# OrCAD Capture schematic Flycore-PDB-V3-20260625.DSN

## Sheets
1 PAGE03_DCDC: size C; title: 分电板; rev: <1>; note: PAGE03_DCDC
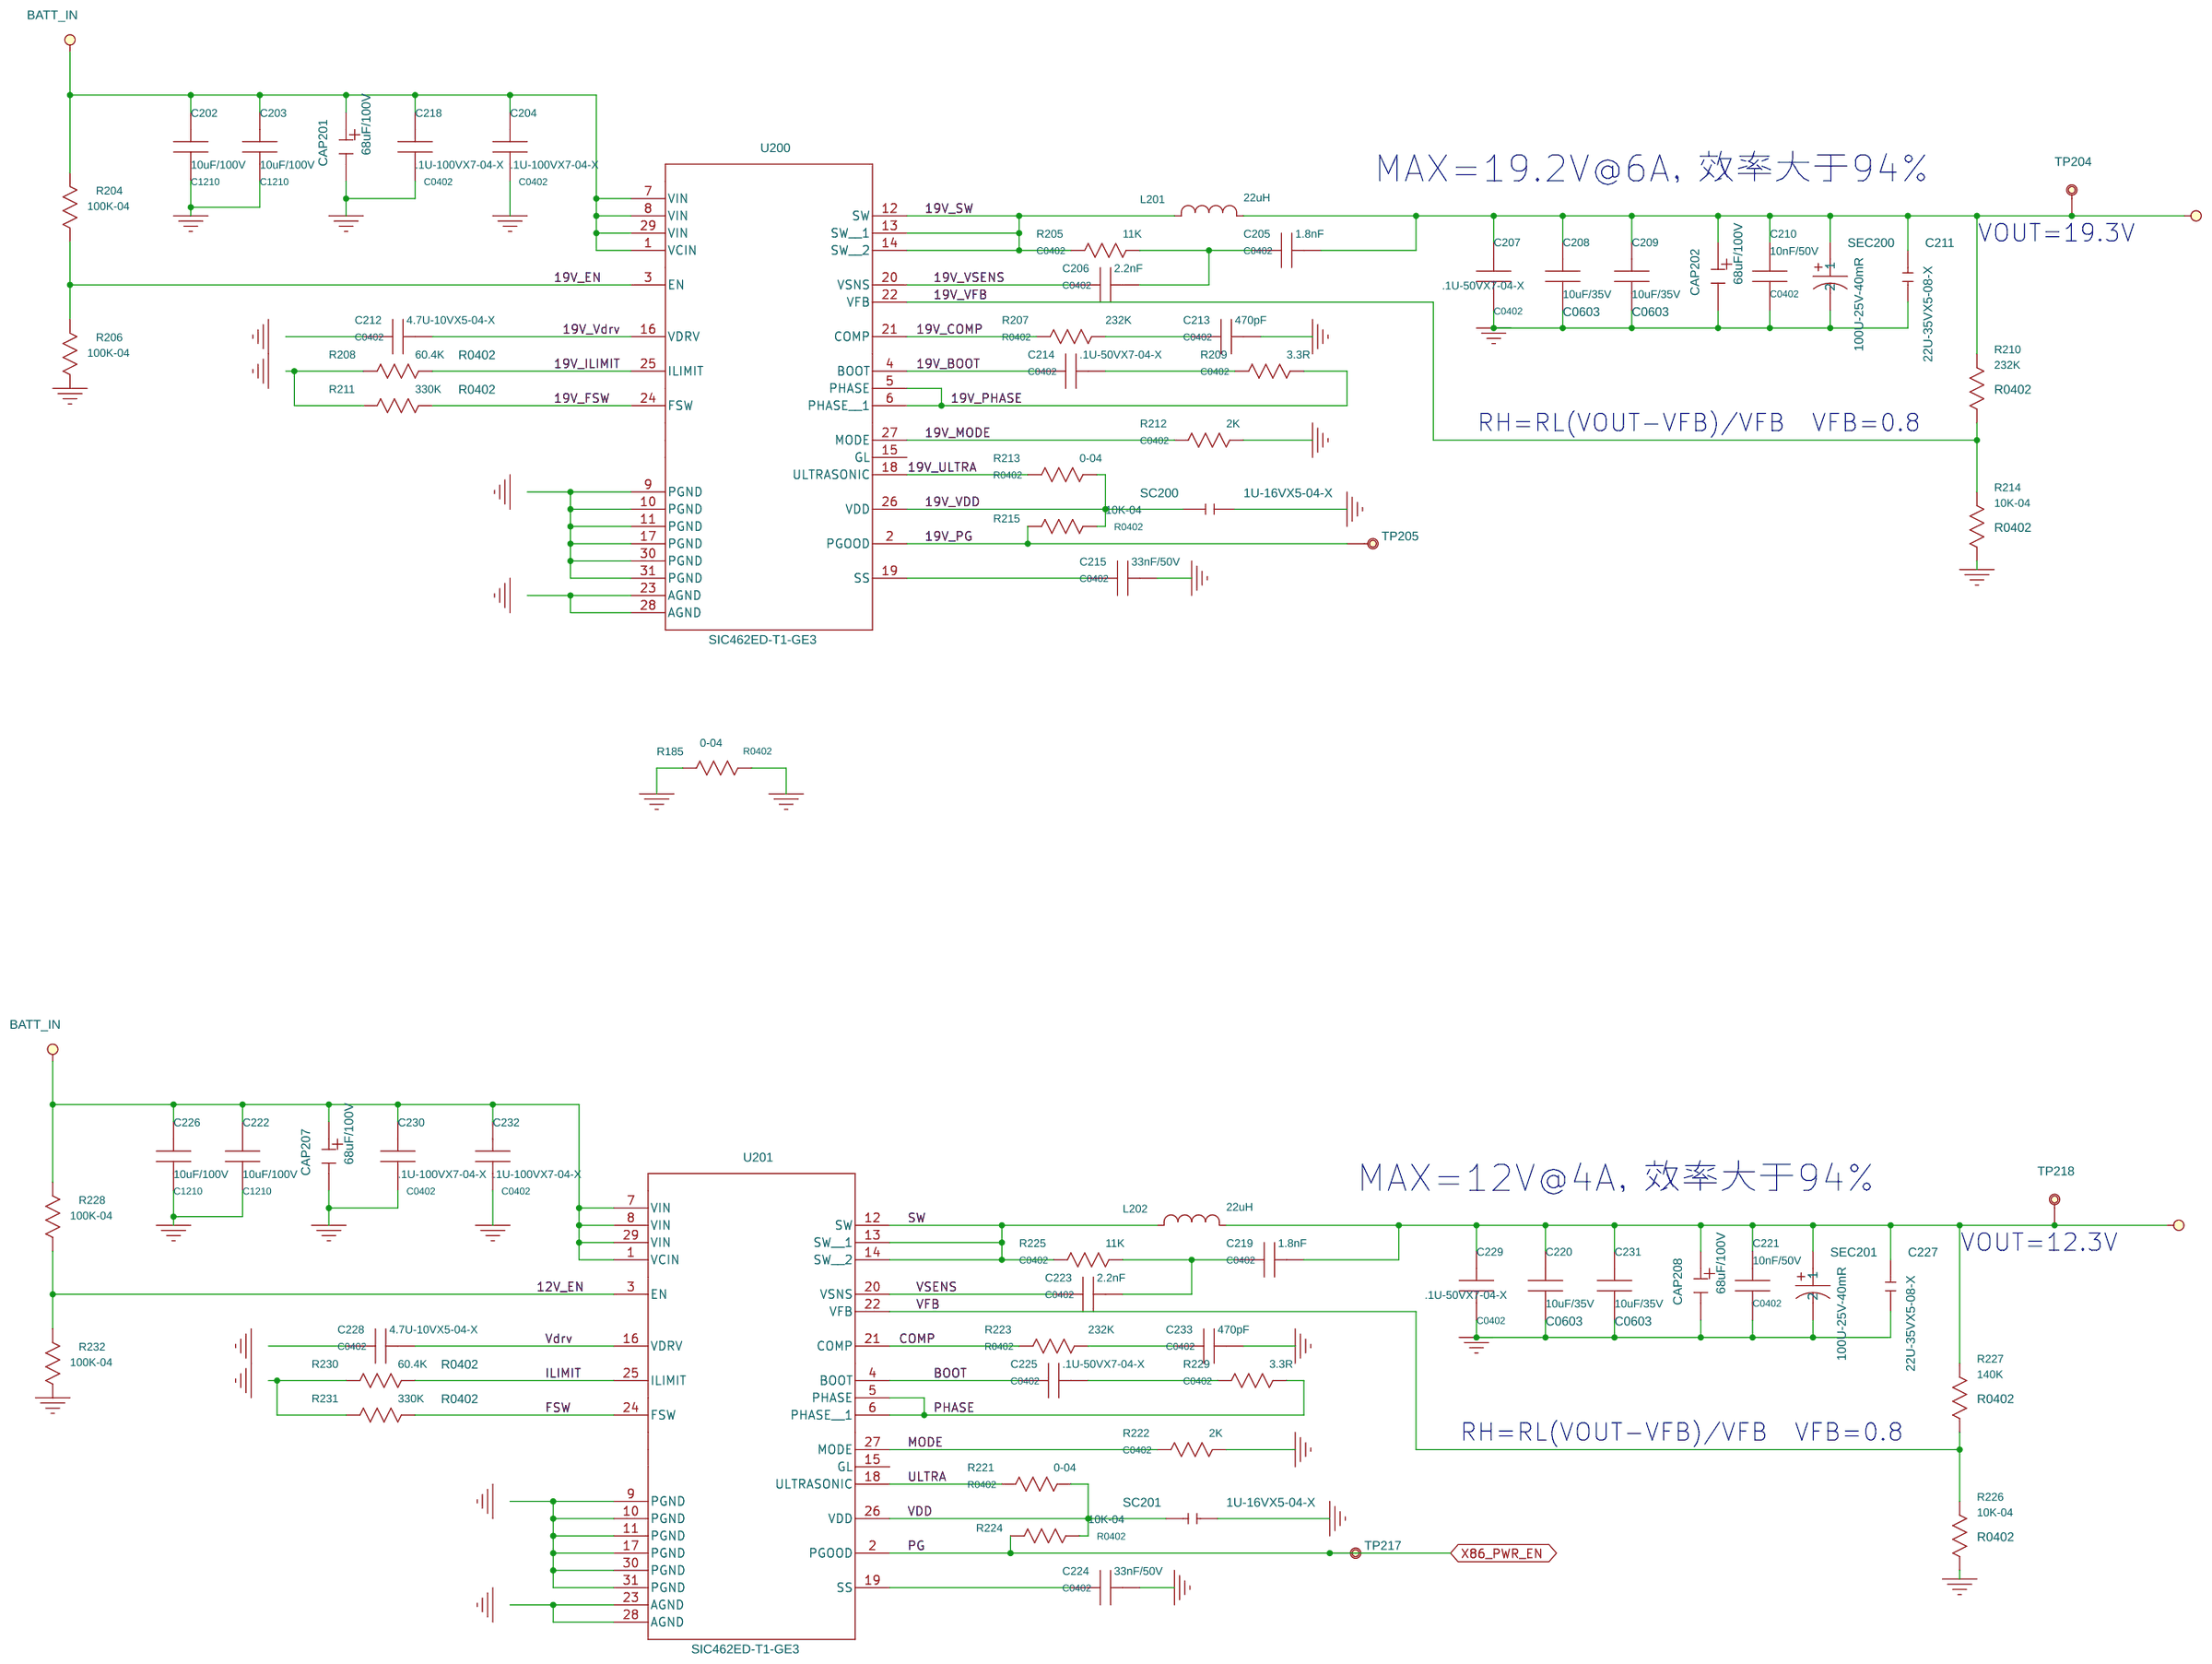
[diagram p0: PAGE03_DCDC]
2 PAGE01_Block Diagram: note: BLOCK DIAGRAM
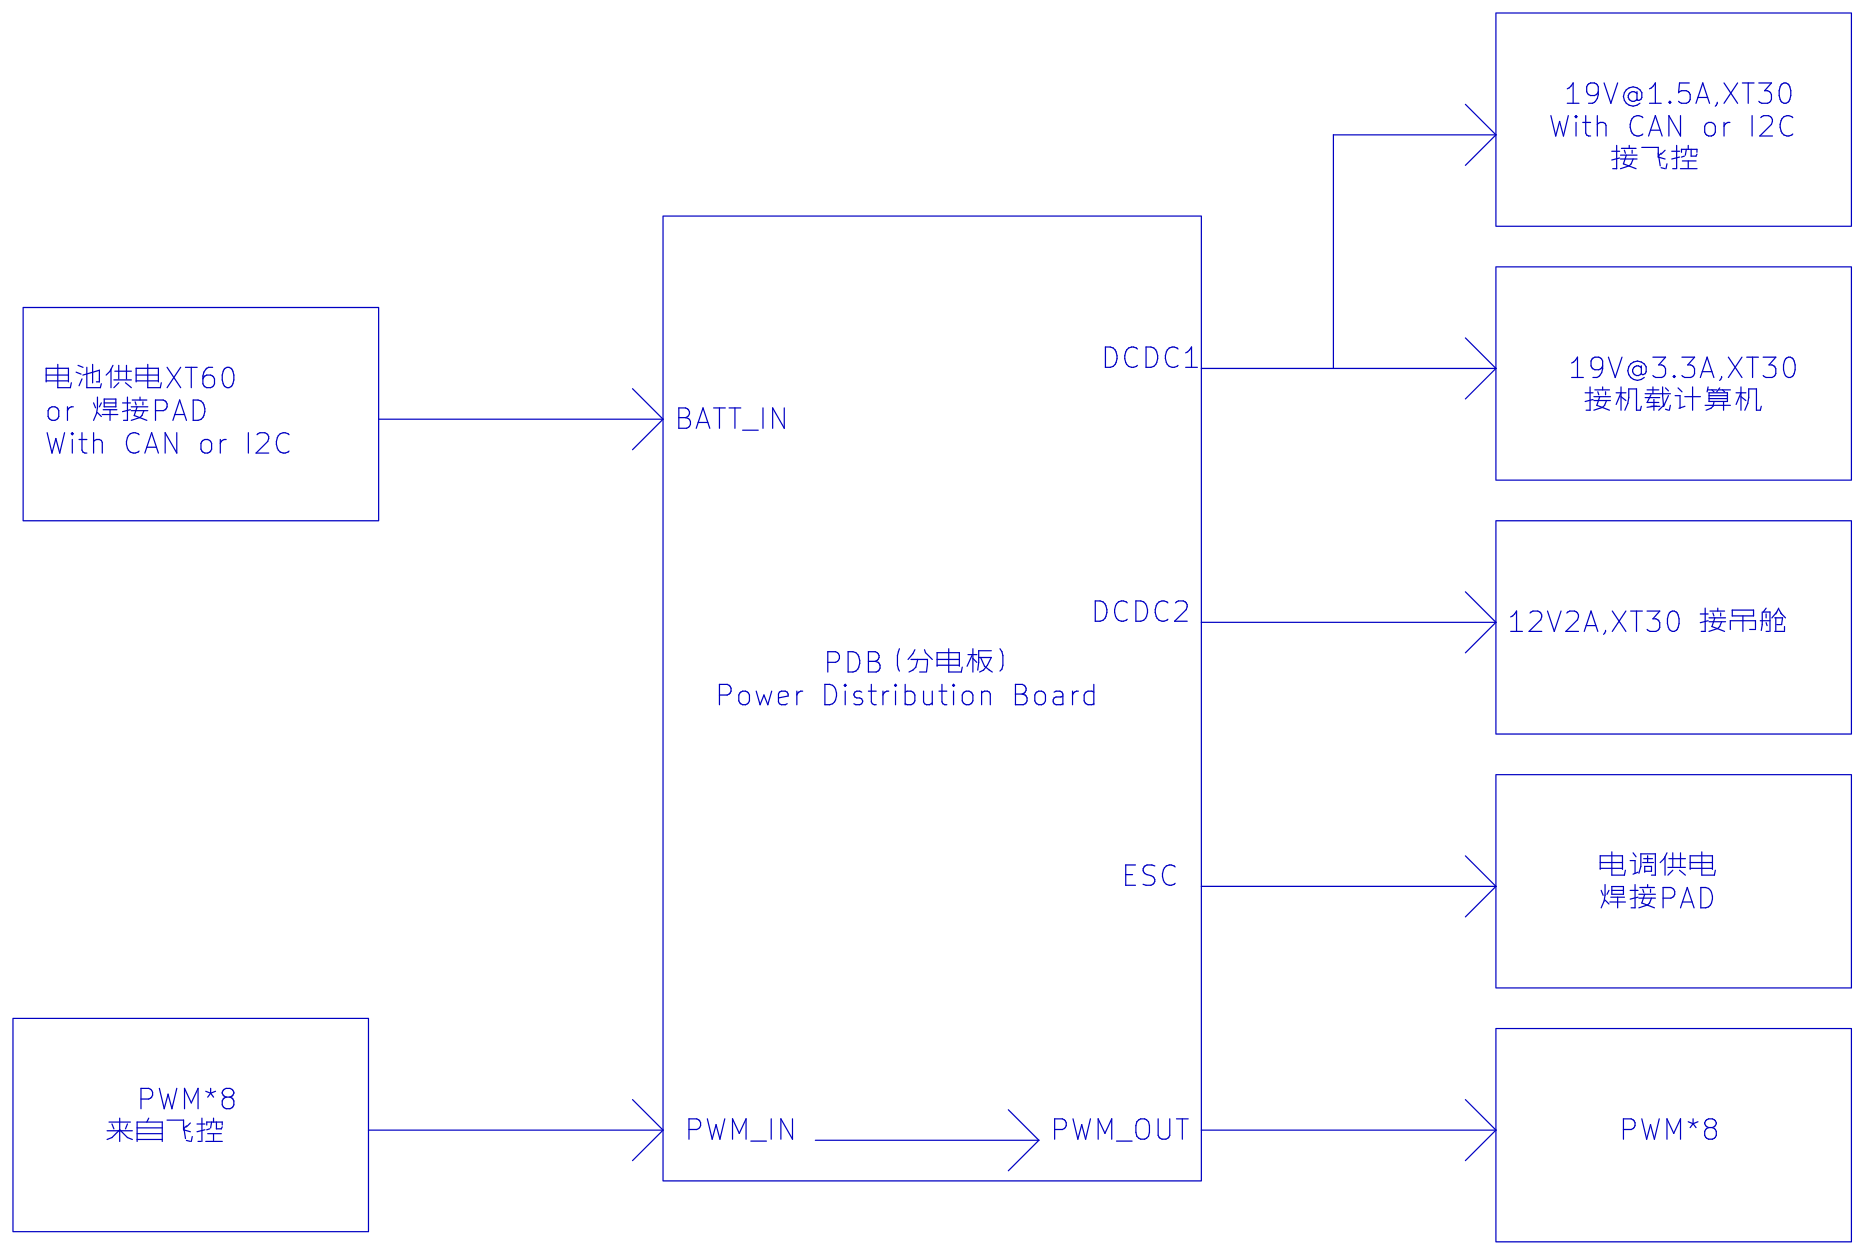
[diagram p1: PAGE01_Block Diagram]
3 PAGE02_Power_Switch: size C; note: PAGE02_Power_Switch
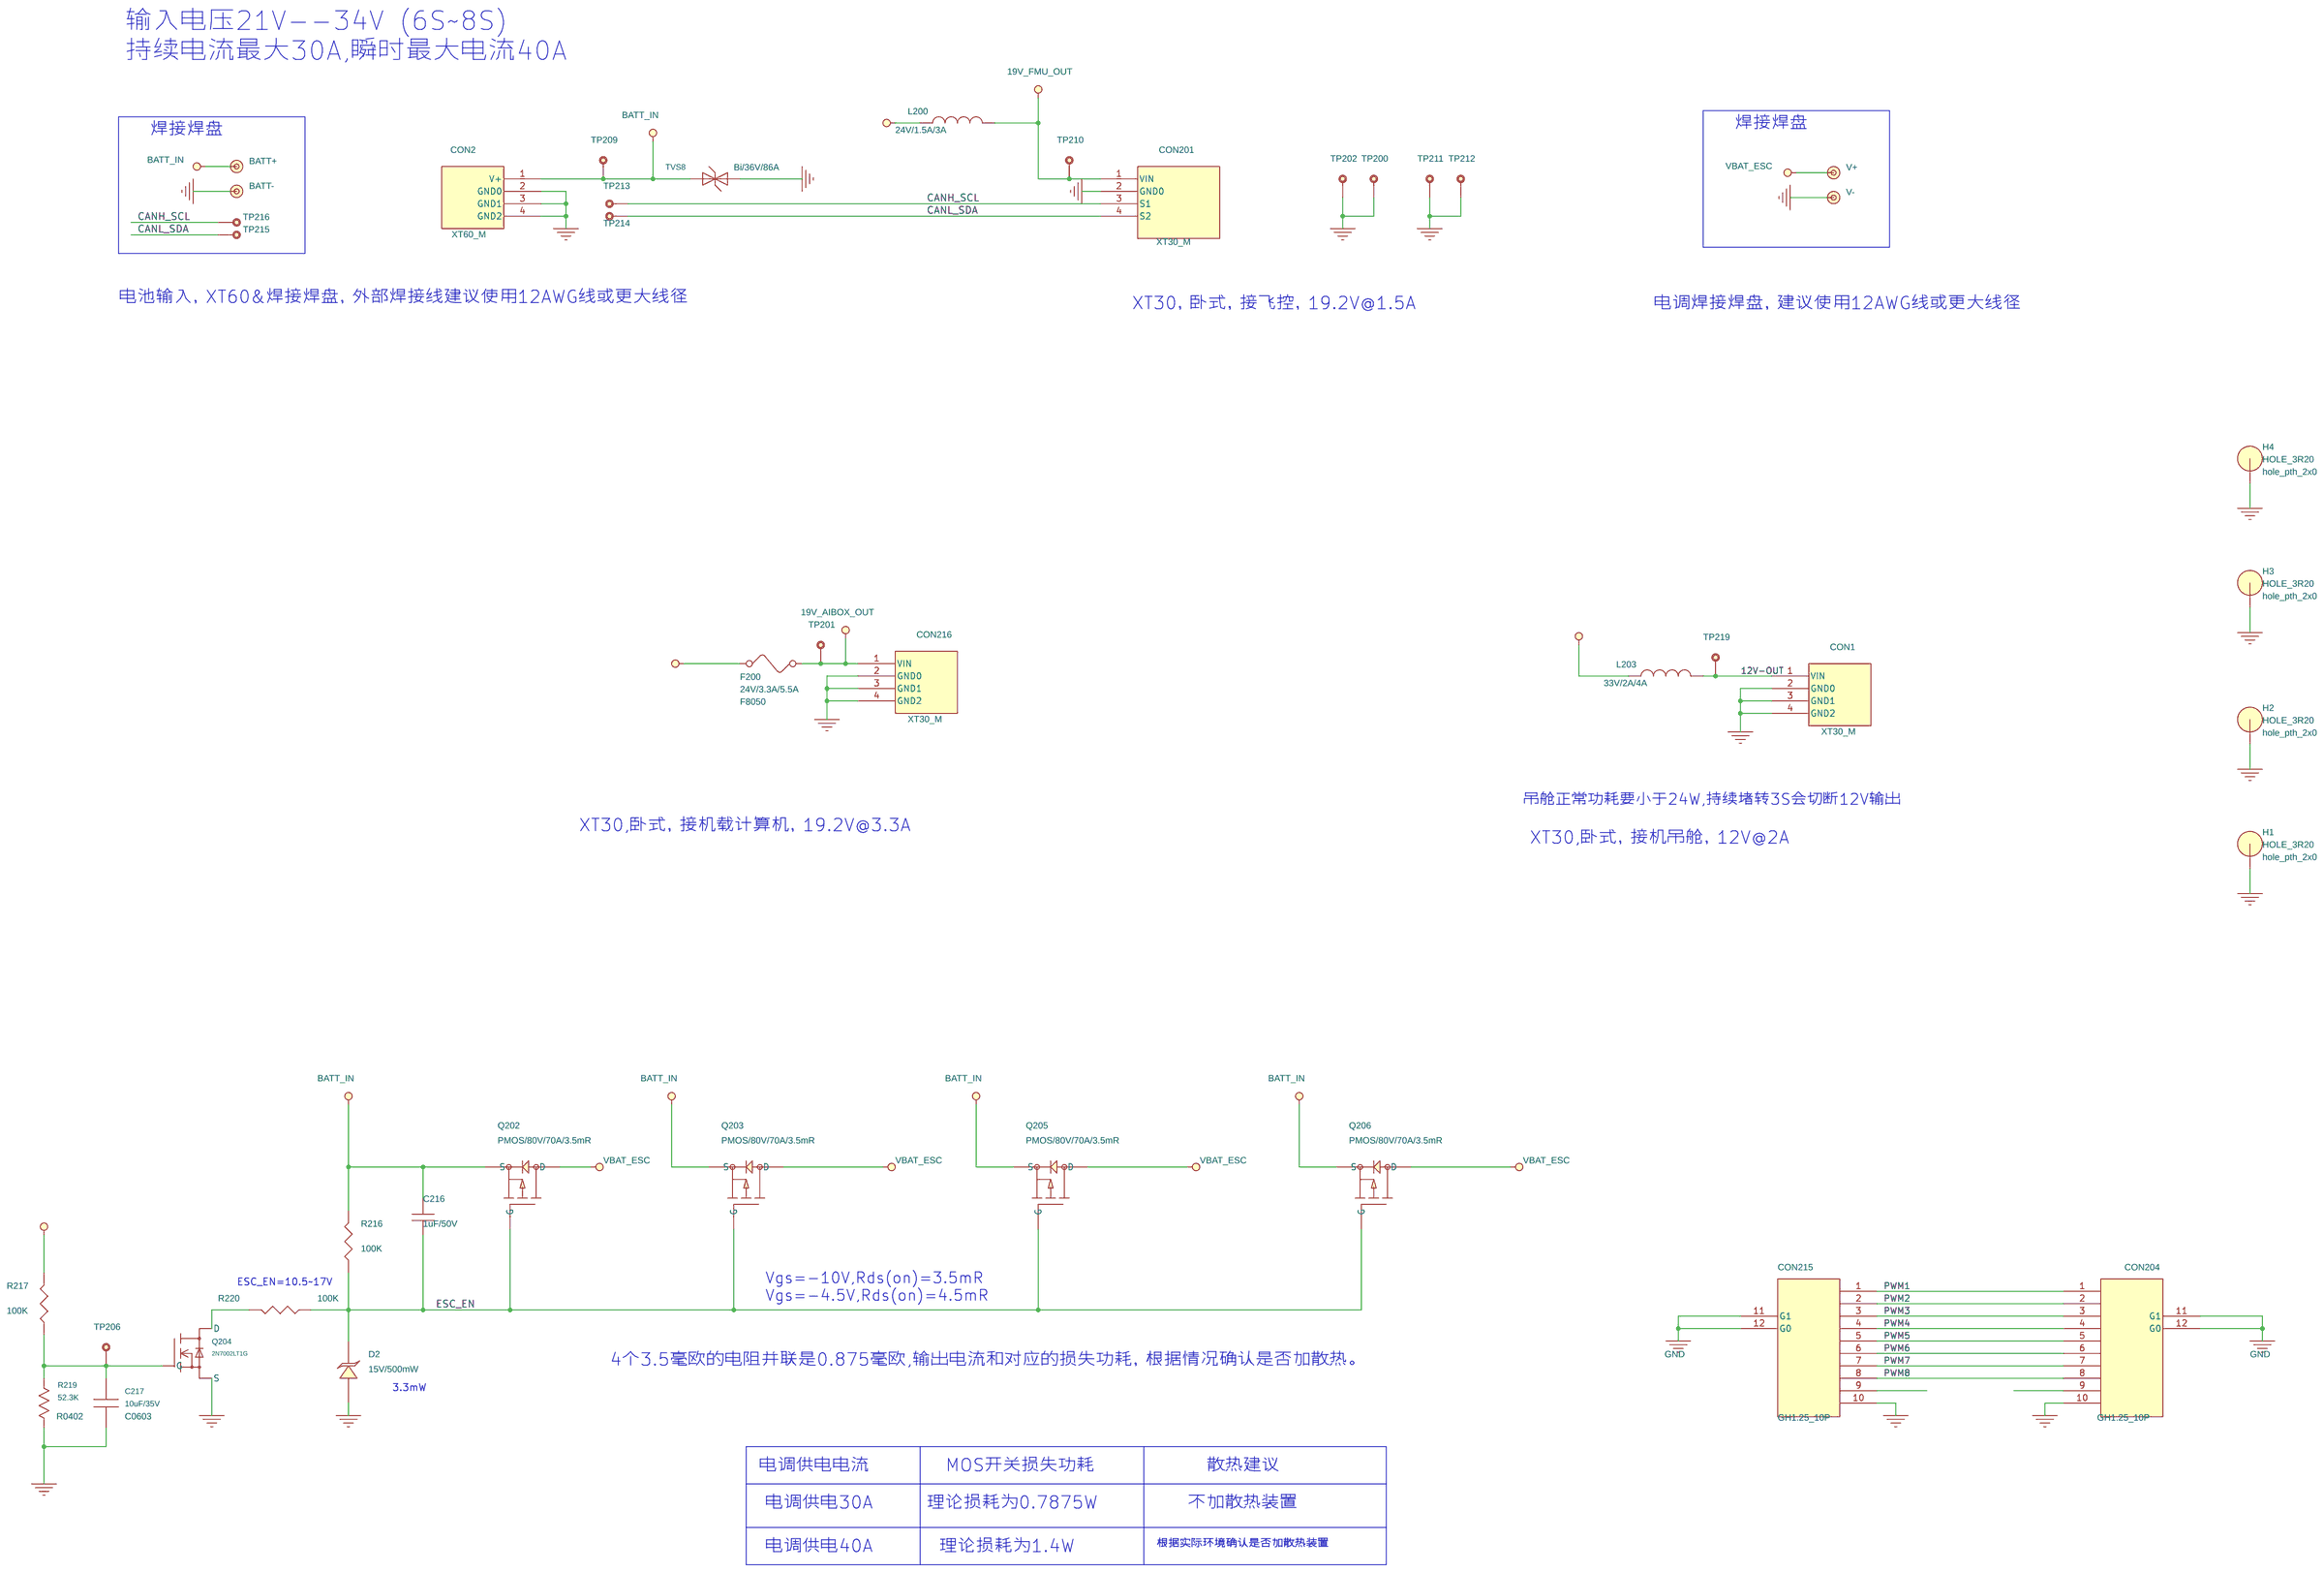
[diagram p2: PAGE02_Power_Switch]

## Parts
sheet PAGE02_Power_Switch
BATT+  TP-SMD  [tp_smd_rect_3r0x4r0]
BATT-  TP-SMD  [tp_smd_rect_3r0x4r0]
C216  1uF/50V  [C0402]
C217  10uF/35V  [C0603]
CON1  XT30_M  [XT30_M]
CON2  XT60_M  [AMASS_XT60PW-M]
CON201  XT30_M  [AMASS_XT30PW2]
CON204  GH1.25_10P  [gh1x25_10_li]
CON215  GH1.25_10P  [gh1x25_10_li]
CON216  XT30_M  [XT30_M]
D2  15V/500mW  [SOD-123]
F200  24V/3.3A/5.5A  [F8050]
H1  HOLE_3R20  [hole_pth_2x0]
H2  HOLE_3R20  [hole_pth_2x0]
H3  HOLE_3R20  [hole_pth_2x0]
H4  HOLE_3R20  [hole_pth_2x0]
L200  24V/1.5A/3A  [C1206]
L203  33V/2A/4A  [r2512]
Q202  PMOS/80V/70A/3.5mR  [to252-3_4r56]
Q203  PMOS/80V/70A/3.5mR  [to252-3_4r56]
Q204  Q_FET_N_ENH  [sot23d132_1_2]
Q205  PMOS/80V/70A/3.5mR  [to252-3_4r56]
Q206  PMOS/80V/70A/3.5mR  [to252-3_4r56]
R216  100K  [R0402]
R217  100K  [R0402]
R219  52.3K  [R0402]
R220  100K  [R0402]
TP200  TP  [testpoint_59mil]
TP201  TP  [testpoint_59mil]
TP202  TP  [testpoint_59mil]
TP206  TP  [testpoint_59mil]
TP209  TP  [testpoint_59mil]
TP210  TP  [testpoint_59mil]
TP211  TP  [testpoint_59mil]
TP212  TP  [testpoint_59mil]
TP213  TP  [testpoint_59mil]
TP214  TP  [testpoint_59mil]
TP215  TP  [testpoint_59mil]
TP216  TP  [testpoint_59mil]
TP219  TP  [testpoint_59mil]
TVS8  Bi/36V/86A  [smc_do-214ab]
V+  TP-SMD  [tp_smd_rect_3r0x4r0]
V-  TP-SMD  [tp_smd_rect_3r0x4r0]
sheet PAGE03_DCDC
C202  10uF/100V  [C1210]
C203  10uF/100V  [C1210]
C204  .1U-100VX7-04-X  [C0402]
C205  1.8nF  [C0402]
C206  2.2nF  [C0402]
C207  .1U-50VX7-04-X  [C0402]
C208  10uF/35V  [C0603]
C209  10uF/35V  [C0603]
C210  10nF/50V  [C0402]
C211  22U-35VX5-08-X  [C0805]
C212  4.7U-10VX5-04-X  [C0402]
C213  470pF  [C0402]
C214  .1U-50VX7-04-X  [C0402]
C215  33nF/50V  [C0402]
C218  .1U-100VX7-04-X  [C0402]
C219  1.8nF  [C0402]
C220  10uF/35V  [C0603]
C221  10nF/50V  [C0402]
C222  10uF/100V  [C1210]
C223  2.2nF  [C0402]
C224  33nF/50V  [C0402]
C225  .1U-50VX7-04-X  [C0402]
C226  10uF/100V  [C1210]
C227  22U-35VX5-08-X  [C0805]
C228  4.7U-10VX5-04-X  [C0402]
C229  .1U-50VX7-04-X  [C0402]
C230  .1U-100VX7-04-X  [C0402]
C231  10uF/35V  [C0603]
C232  .1U-100VX7-04-X  [C0402]
C233  470pF  [C0402]
CAP201  68uF/100V  [cap_smd_330_D10]
CAP202  68uF/100V  [cap_smd_330_D10]
CAP207  68uF/100V  [cap_smd_330_D10]
CAP208  68uF/100V  [cap_smd_330_D10]
L201  22uH  [L_11X15_10X85]
L202  22uH  [L_11X15_10X85]
R185  0-04  [R0402]
R204  100K-04  [C0402]
R205  11K  [C0402]
R206  100K-04  [C0402]
R207  232K  [R0402]
R208  60.4K  [R0402]
R209  3.3R  [C0402]
R210  232K  [R0402]
R211  330K  [R0402]
R212  2K  [C0402]
R213  0-04  [R0402]
R214  10K-04  [R0402]
R215  10K-04  [R0402]
R221  0-04  [R0402]
R222  2K  [C0402]
R223  232K  [R0402]
R224  10K-04  [R0402]
R225  11K  [C0402]
R226  10K-04  [R0402]
R227  140K  [R0402]
R228  100K-04  [C0402]
R229  3.3R  [C0402]
R230  60.4K  [R0402]
R231  330K  [R0402]
R232  100K-04  [C0402]
SC200  1U-16VX5-04-X  [C0402]
SC201  1U-16VX5-04-X  [C0402]
SEC200  100U-25V-40mR  [C7343]
SEC201  100U-25V-40mR  [C7343]
TP204  TP  [testpoint_59mil]
TP205  TP  [testpoint_59mil]
TP217  TP  [testpoint_59mil]
TP218  TP  [testpoint_59mil]
U200  SIC462ED-T1-GE3  [VREG_SIC462ED-T1-GE3]
U201  SIC462ED-T1-GE3  [VREG_SIC462ED-T1-GE3]

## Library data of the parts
BATT+ BATT- V+ V- = TP: 测试点; BOM_Manufacturer_Part: PART_NUM; OPTION: 不焊接; PRICE: 0; SMTProperty: 不焊接
C216 = CAP_0: MANUFACTURER: YAGEO; MPN: CC0402KRX5R8BB104; Manufacture: HRE; part number: CGA0402X5R105K500GT
C208 C209 C217 C220 C231 = C#1: MANUFACTURER: muRata; Manufacture: muRata; part number: GRM188R6YA106MA73D
CON1 CON216 = XT30_M: Manufacture: AMASS; part number: XT30PW-M
CON2 = XT30_M_51: Manufacture: AMASS; part number: XT60PW_M
CON201 = XT30_M_46: Manufacture: AMASS; part number: XT30PW(2+2)-M.G.B
CON204 CON215 = XT30_M_5: MANUFACTURER: JST; Manufacture: JST; part number: GH125-S10CCA-00
D2 = TVS_0: ERP类型: TVS; Manufacture: MDD(辰达半导体); part number: BZT52C15
F200 = FUSE: 保险丝，Vmax=16V,Imax=100A，Icurrent=8A,Ri=0.028ohm; Created by: JJJ; Manufacture: Littelfuse; Manufacturer: 金瑞电子; Manufacturer Part Number: Q/JKTD-16-200; Priority: A; RK PN: Q/JKTD-16-200; part number: 2920L330/24MR
H1-H4 = Hole: 直径3.2mm螺丝孔,无铜柱; Created by: YWQ; Part Type: HOLE; Priority: A
L200 = INDUCTOR: 抗30±10Ω,最大直流电阻（DCR）0.01Ω，最大电流6A; Manufactory Footprint: L0805; Manufactory Name: TDK; Manufacture: LUTE; Material Code: 503040004; Optimum Level: D; Ordering Information: MPZ2012S300A; Part Type: Bead; Quality Level: I; part number: 1206L150/24NR
L203 = INDUCTOR: 抗30±10Ω,最大直流电阻（DCR）0.01Ω，最大电流6A; Manufactory Footprint: L0805; Manufactory Name: TDK; Manufacture: LUTE; Material Code: 503040004; Optimum Level: D; Ordering Information: MPZ2012S300A; Part Type: Bead; Quality Level: I; part number: 2512L200/33GR
Q202 Q203 Q205 Q206 = PMOS-1: P-Mos,SOT-23,CJ2303,30V,330mΩ@4.5V,JCET,CJ2303,3*2.55*1.15; MF_PARTNUMBER: CJ2303; Manufacture: HUASHUO; PART_TYPE: P-Mos; part number: HSU4119; Datasheet: L:\Skysofy-SPEC\Mos&Tri&Dio_ITEMS\222-0003-001.pdf
Q204 = Q_FET_N_ENH#1: ASSEMBLY: M2_WIFIBT; CDS_LIB: discrete; CDS_LOCATION: Q17; CDS_PART_NAME: Q_FET_N_ENH_DFN1006-DMN26D0UFB4,20V,999MOHM@10V / 3000MOHM@4.5V / 4000MOHM@2.5V,0.14A,0.805A,10V,0.35W,999NC@10V / 0NC@4.5V / A; CDS_PHYS_PART_NAME: Q_FET_N_ENH_DFN1006-DMN26D0UFB4,20V,999MOHM@10V / 3000MOHM@4.5V / 4000MOHM@2.5V,0.14A,0.805A,10V,0.35W,999NC@10V / 0NC@4.5V / B; CDS_SEC: 1; CONTINUOUS_CURRENT: 0.14A; CaptureCellPackProp: Q_FET_N_ENH##1; DEVICE_TYPENAME: Q_FET_N_ENH_DFN1006-DMN26D0UFB420V999MOHM10V3000MOHM45V4000MOHM25V014A0805A10V035W999NC10V0NC45VB; DRAWING: #NAME?; LOCATION: Q17; MAX_CURRENT: 0.805A; MAX_VOLTAGE: 20V; MAX_WATTAGE: 0.35W; Manufacture: onsemi; NV_NAME: 2N7002LT1G; NV_PN: 300-0868-000; PACK_TYPE: DFN1006; PATH: I73; part number: 2N7002LT1G
R216 R220 = R_v3: RES,0402,100K,1/16W,5%,RALEC旺诠,RTT02104JTH,1.0*0.5*0.35; MF_PARTNUMBER: RTT02104JTH; Manufacture: YAGEO; PART_TYPE: RES; part number: RC0402FR-07100KL; Datasheet: L:\Skysofy-SPEC\RLC_ITEMS\100-0024-002.pdf
R217 = R_v3: RES,0402,10K,1/16W,5%,RALEC旺诠,RTT02103JTH,1.0*0.5*0.35; MF_PARTNUMBER: RTT02103JTH; Manufacture: YAGEO; PART_TYPE: RES; part number: RC0402FR-07100KL; Datasheet: L:\Skysofy-SPEC\RLC_ITEMS\100-0026-002.pdf
R219 = R: Manufacture: FOJAN; part number: FRC0402F5232TS
TP200-TP202 TP204-TP206 TP209-TP219 = TP_v2: I16774898: I16774971
TVS8 = D_ESD: Manufacture: DOWO; part number: 5.0SMDJ36CA
C202 C203 C222 C226 = C#1: MANUFACTURER: muRata; Manufacture: PSA; part number: FS32X106K101EGG
C204 C218 C230 C232 = C#1: MANUFACTURER: muRata; Manufacture: muRata; part number: GRM155R62A104KE14D
C205 C219 = C#1: MANUFACTURER: muRata; Manufacture: YAGEO; part number: CC0402KRX7R9BB182
C206 C223 = C#1: MANUFACTURER: muRata; Manufacture: muRata; part number: GRM1555C1H222GA01D
C207 C214 C225 C229 = C#1: MANUFACTURER: muRata; Manufacture: YAGEO; part number: CC0402KRX7R9BB104
C210 C221 = C#1: MANUFACTURER: muRata; Manufacture: YAGEO; part number: CC0402KRX7R9BB103
C211 C227 = C0805: C/C.10uF.25V.10%..X5R..T=1.25mm..SMD 0805....LEAD-FREE(RoHS/HF)..; INVENTORY_ON_HAND: 1,743,250; Item_Status: Active; Manufacture: TDK; Part Number: C2012X5R1V226MT000E; Part Type: SMT; VMI_HUB_ON_HAND: 586,000
C212 C228 = C#1: MANUFACTURER: muRata; Manufacture: SAMSUNG; part number: CL05A475KP5NRNC
C213 C233 = C#1: MANUFACTURER: muRata; Manufacture: muRata; part number: GRM1555C1H471JA01D
C215 C224 = C#1: MANUFACTURER: muRata; Manufacture: FOJAN; part number: FCC0402B333K500AT
CAP201 CAP202 CAP207 CAP208 = ECP_0: 贴片电解电容; HelpURL: https://item.szlcsc.com/345306.html; Manufacture: HONOR(荣誉); PRICE: 0.6241; T_TEMPERATURE: -55℃~+155℃; Tolerance: 20%; Vendor: CX(承兴); Vendor P/N: 250AVHA470M0606; part number: HV2A686M1010PZ; 耐压: 25V
L201 L202 = L: Manufacture: PROD; part number: PSPMAA1082T-220M-CGP
R185 R213 R221 = R: Manufacture: UNI-ROYAL; part number: 0402WGF0000TCE
R204 R206 R228 R232 = R: Manufacture: UNI-ROYAL; part number: 0402WGF1003TCE
R205 R225 = R: Manufacture: FOJAN; part number: FRC0402J113 TS
R207 R210 R223 = R: Manufacture: FOJAN; part number: FRC0402F2323TS
R208 R230 = R: Manufacture: FOJAN; part number: FRC0402F6042TS
R209 R229 = R: Manufacture: FOJAN; part number: FRC0402F3R30TS
R211 R231 = R: Manufacture: FOJAN; part number: FRC0402F3303TS
R212 R222 = R: Manufacture: FOJAN; part number: FRC0402F2001TS
R214 R215 R224 R226 = R: Manufacture: UNI-ROYAL; part number: 0402WGF1002TCE
R227 = R: Manufacture: FOJAN; part number: FRC0402F1433TS
SC200 SC201 = C0402: C/C.1uF.6.3V.10%..X5R....SMD 0402....LEAD-FREE(RoHS/HF).; INVENTORY_ON_HAND: 3,432,041; Item_Status: Active; Manufacture: SAMSUNG; Part Number: CL05A105KO5NNNC; Part Type: SMT; VMI_HUB_ON_HAND: 8,620,000
SEC200 SEC201 = CAPACITOR_POL_0: T/C POLYMER.33uF.16V.20%.90m OHM...105C..16TQC33MYFB.SMD B2....LEAD-FREE(RoHS/HF).PANASONIC; Manufacture: KEMET; Part Number: T521D107M025ATE040
U200 U201 = SIC462ED-T1-GE3_7: Manufacture: VISHAY

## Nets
12V-OUT: CON1.1(VIN) L203.2 TP219.1
12V_EN: R228.2 R232.1 U201.3(EN)
19V_AIBOX_OUT: CON216.1(VIN) F200.2 TP201.1
19V_BOOT: C214.1 U200.4(BOOT)
19V_COMP: R207.1 U200.21(COMP)
19V_EN: R204.2 R206.1 U200.3(EN)
19V_FMU_OUT: CON201.1(VIN) L200.2 TP210.1
19V_FSW: R211.2 U200.24(FSW)
19V_ILIMIT: R208.2 U200.25(ILIMIT)
19V_MODE: R212.1 U200.27(MODE)
19V_PG: R215.1 TP205.1 U200.2(PGOOD)
19V_PHASE: R209.2 U200.5(PHASE) U200.6(PHASE__1)
19V_SW: L201.1 R205.1 U200.12(SW) U200.13(SW__1) U200.14(SW__2)
19V_ULTRA: R213.1 U200.18(ULTRASONIC)
19V_VDD: R213.2 R215.2 SC200.1 U200.26(VDD)
19V_Vdrv: C212.1 U200.16(VDRV)
19V_VFB: R210.2 R214.1 U200.22(VFB)
19V_VSENS: C206.2 U200.20(VSNS)
AGND: C204.2 C213.1 C215.2 C224.2 C232.2 C233.1 R185.1 R208.1 R211.1 R212.2 R214.2 R222.2 R226.2 R230.1 R231.1 SC200.2 SC201.2 U200.23(AGND) U200.28(AGND) U201.23(AGND) U201.28(AGND)
GND: BATT-.1 C202.2 C203.2 C207.2 C208.2 C209.2 C210.2 C211.2 C212.2 C217.2 C218.2 C220.2 C221.2 C222.2 C226.2 C227.2 C228.2 C229.2 C230.2 C231.2 CAP201.2 CAP202.2 CAP207.2 CAP208.2 CON1.2(GND0) CON1.3(GND1) CON1.4(GND2) CON2.2(GND0) CON2.3(GND1) CON2.4(GND2) CON201.2(GND0) CON204.10 CON204.11(G1) CON204.12(G0) CON215.10 CON215.11(G1) CON215.12(G0) CON216.2(GND0) CON216.3(GND1) CON216.4(GND2) D2.2(ANODE) H1.1 H2.1 H3.1 H4.1 Q204.2(S) R185.2 R206.2 R219.1 R232.2 SEC200.2 SEC201.2 TP200.1 TP202.1 TP211.1 TP212.1 TVS8.2 U200.9(PGND) U200.10(PGND) U200.11(PGND) U200.17(PGND) U200.30(PGND) U200.31(PGND) U201.9(PGND) U201.10(PGND) U201.11(PGND) U201.17(PGND) U201.30(PGND) U201.31(PGND) V-.1
VBAT_ESC: Q202.3(D) Q203.3(D) Q205.3(D) Q206.3(D) V+.1
VDD: R221.2 R224.2 SC201.1 U201.26(VDD)
VDD_12V_SYS: C219.1 C220.1 C221.1 C227.1 C229.1 C231.1 CAP208.1 L202.2 L203.1 R227.1 SEC201.1 TP218.1
VDD_19V_SYS: C205.1 C207.1 C208.1 C209.1 C210.1 C211.1 CAP202.1 F200.1 L200.1 L201.2 R210.1 R217.2 SEC200.1 TP204.1
BATT_IN: BATT+.1 C202.1 C203.1 C204.1 C216.2 C218.1 C222.1 C226.1 C230.1 C232.1 CAP201.1 CAP207.1 CON2.1(V+) Q202.2(S) Q203.2(S) Q205.2(S) Q206.2(S) R204.1 R216.2 R228.1 TP209.1 TVS8.1 U200.1(VCIN) U200.7(VIN) U200.8(VIN) U200.29(VIN) U201.1(VCIN) U201.7(VIN) U201.8(VIN) U201.29(VIN)
BOOT: C225.1 U201.4(BOOT)
CANH_SCL: CON201.3(S1) TP213.1 TP216.1
CANL_SDA: CON201.4(S2) TP214.1 TP215.1
COMP: R223.1 U201.21(COMP)
ESC_EN: C216.1 D2.1(CATHODE) Q202.1(G) Q203.1(G) Q205.1(G) Q206.1(G) R216.1 R220.1
FSW: R231.2 U201.24(FSW)
ILIMIT: R230.2 U201.25(ILIMIT)
MODE: R222.1 U201.27(MODE)
PHASE: R229.2 U201.5(PHASE) U201.6(PHASE__1)
PWM1: CON204.1 CON215.1
PWM2: CON204.2 CON215.2
PWM3: CON204.3 CON215.3
PWM4: CON204.4 CON215.4
PWM5: CON204.5 CON215.5
PWM6: CON204.6 CON215.6
PWM7: CON204.7 CON215.7
PWM8: CON204.8 CON215.8
SW: L202.1 R225.1 U201.12(SW) U201.13(SW__1) U201.14(SW__2)
ULTRA: R221.1 U201.18(ULTRASONIC)
Vdrv: C228.1 U201.16(VDRV)
VFB: R226.1 R227.2 U201.22(VFB)
VSENS: C223.2 U201.20(VSNS)
X86_PWR_EN: R224.1 TP217.1 U201.2(PGOOD)
N8283759: C217.1 Q204.1(G) R217.1 R219.2 TP206.1
N15887710: Q204.3(D) R220.2
N17226372: C205.2 C206.1 R205.2
N17226390: C213.2 R207.2
N17226393: C214.2 R209.1
N17226422: C215.1 U200.19(SS)
N17229988: C219.2 C223.1 R225.2
N17230026: C233.2 R223.2
N17230033: C225.2 R229.1
N17230097: C224.1 U201.19(SS)

Not connected (* = marked no-connect by the designer): CON204 9; CON215 9; U200 15(GL); U201 15(GL)

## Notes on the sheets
sheet 1
- MAX=19.2V@6A，效率大于94%
- VOUT=19.3V
- RH=RL(VOUT-VFB)/VFB  VFB=0.8
- MAX=12V@4A，效率大于94%
- VOUT=12.3V
- RH=RL(VOUT-VFB)/VFB  VFB=0.8
sheet 2
- 19V@1.5A,XT30
    With CAN or I2C
        接飞控
- DCDC1
- 电池供电XT60
  or 焊接PAD
  With CAN or I2C
- 19V@3.3A,XT30
   接机载计算机
- BATT_IN
- DCDC2
- 12V2A,XT30 接吊舱
- PDB（分电板）
  Power Distribution Board
- ESC
- 电调供电
  焊接PAD
- PWM*8
  来自飞控
- PWM_IN
- PWM_OUT
- PWM*8
sheet 3
- 输入电压21V--34V (6S~8S)
  持续电流最大30A,瞬时最大电流40A
- 焊接焊盘
- 焊接焊盘
- 电池输入，XT60&焊接焊盘，外部焊接线建议使用12AWG线或更大线径
- XT30，卧式，接飞控，19.2V@1.5A
- 电调焊接焊盘，建议使用12AWG线或更大线径
- 吊舱正常功耗要小于24W,持续堵转3S会切断12V输出
- XT30,卧式，接机载计算机，19.2V@3.3A
- XT30,卧式，接机吊舱，12V@2A
- Vgs=-10V,Rds(on)=3.5mR
  Vgs=-4.5V,Rds(on)=4.5mR
- ESC_EN=10.5~17V
- 4个3.5毫欧的电阻并联是0.875毫欧,输出电流和对应的损失功耗，根据情况确认是否加散热。
- 3.3mW
- 电调供电电流
- MOS开关损失功耗
- 散热建议
- 电调供电30A
- 理论损耗为0.7875W
- 不加散热装置
- 电调供电40A
- 理论损耗为1.4W
- 根据实际环境确认是否加散热装置
